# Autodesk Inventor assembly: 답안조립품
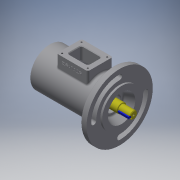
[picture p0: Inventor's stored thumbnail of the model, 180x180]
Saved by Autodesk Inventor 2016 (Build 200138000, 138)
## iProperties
Created: 2017-05
Part Number: 답안조립품
Material: 일반
Document SubType Name: Assembly
Designer: USER
Author: USER
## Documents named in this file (6)
- C:\Users\USER\Desktop\470508V1005\답안조립품.iam
- C:\Users\USER\Desktop\470508V1005\본체.ipt
- C:\Users\USER\Desktop\470508V1005\부시1.ipt
- C:\Users\USER\Desktop\470508V1005\축.ipt
- C:\Users\USER\Desktop\470508V1005\키 4 x 4 x 18.ipt
- C:\Users\USER\Desktop\470508V1005\베어링 15 x 35 x 11.ipt
